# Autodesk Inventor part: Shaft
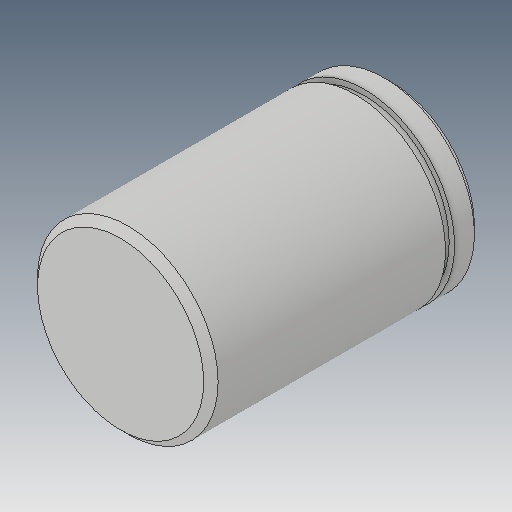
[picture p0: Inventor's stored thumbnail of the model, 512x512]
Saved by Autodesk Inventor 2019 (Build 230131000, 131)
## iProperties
Created: 2016-08
Part Number: Shaft
Material: Generic
Document SubType Name: Modeling
Designer: Sandeep
Density: 1 g/cm^3
Appearance: Default
Author: Sandeep
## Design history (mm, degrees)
sketch "Sketch1"
  geometry: C1 r 25 at (0, 0); 1 further point
  constraints: 1 centre point, 1 coincident
  dimensions: "d0" = 50 diameter of C1
extrude "Extrusion1" new body sketch "Sketch1" stored distance "d1" = 75; taper "d2" = 0 deg
sketch "Sketch2"
  geometry: L1 (-25, -37.5)-(-25, 37.5) reference; L2 (-25, -30)-(-23.5, -30); L3 (-23.5, -30)-(-23.5, -27.5); L4 (-23.5, -27.5)-(-25, -27.5); L5 (-25, -27.5)-(-25, -30); L6 (0, 0)-(0, -83)
  constraints: 10 end point, 2 parallel, 1 horizontal, 1 perpendicular, 1 point on line, 1 vertical
  dimensions: "d3" = 2.5 distance between parallel lines of L2 L4; "d4" = 47 diameter of L3 L6; "d5" = 7.5 distance from line of L2 L1.start
revolve "Revolution1" sketch "Sketch2" stored, may be unused: angle "d6" = 90 deg
chamfer "Chamfer1" distance "d7" = 2; stored, may be unused: second distance "d8" = 2, angle "d9" = 45 deg
body "Solid1"
other parameters: "d10" = 0
